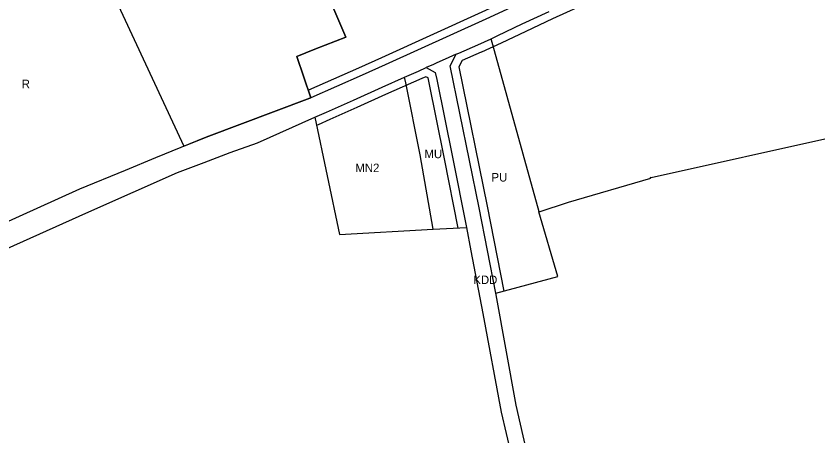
# Model space of a CAD drawing. Extents: x 7435758 to 7439981, y 5550649 to 5554049.
# Drawn here: x 7436617.4 to 7437108.2, y 5551241.1 to 5551497.9 of the extents above; entities that cross this region are included whole.
import ezdxf

# ---------------------------------------------------------------- set-up
doc = ezdxf.new("R2010")
doc.units = 0
for name, color, linetype in [('_Tereny dla których obowiązuje MPZP', 7, 'Continuous'), ('linie_rozgraniczające', 7, 'Continuous'), ('linie_zabudowy_nieprzekraczalne', 7, 'Continuous'), ('oznaczenia_przeznaczen', 7, 'Continuous')]:
    doc.layers.add(name, color=color, linetype=linetype)

msp = doc.modelspace()

# ---------------------------------------------------------------- linework, layer by layer
at = {"layer": '_Tereny dla których obowiązuje MPZP'}
for p, q in [((7436819.25, 5551484.94), (7436803.56, 5551521.54)), ((7436733.75, 5551423.85), (7436797.32, 5551447.57))]:
    msp.add_line(p, q, dxfattribs=at)
for points in [[(7436574.58, 5551700.76), (7436585.89, 5551706.11), (7436720.07, 5551418.24), (7436733.75, 5551423.85)], [(7436789.24, 5551473.16), (7436800.3, 5551477.56), (7436819.25, 5551484.94)], [(7436797.32, 5551447.57), (7436797.85, 5551447.8), (7436789.24, 5551473.16)]]:
    msp.add_lwpolyline(points, dxfattribs=at)
at = {"layer": 'linie_rozgraniczające'}
for p, q in [((7436803.56, 5551521.54), (7436819.25, 5551484.94)), ((7436819.25, 5551484.94), (7436803.56, 5551521.54)), ((7436944.46, 5551514.32), (7436904.86, 5551495.96)), ((7436927.29, 5551493.04), (7436943.73, 5551500.73)), ((7436904.86, 5551495.96), (7436843.44, 5551467.97)), ((7436912.27, 5551485.93), (7436927.29, 5551493.04)), ((7436819.25, 5551484.94), (7436800.3, 5551477.56)), ((7436900.15, 5551480.36), (7436908.19, 5551484.06)), ((7436908.19, 5551484.06), (7436912.27, 5551485.93)), ((7436937.68, 5551378.18), (7436908.19, 5551484.06)), ((7436888.4, 5551475.2), (7436900.15, 5551480.36)), ((7436800.3, 5551477.56), (7436789.24, 5551473.16)), ((7436789.24, 5551473.16), (7436797.85, 5551447.8)), ((7436886.77, 5551474.48), (7436882.22, 5551472.45)), ((7436883.22, 5551467.5), (7436886.77, 5551474.48)), ((7436886.77, 5551474.48), (7436888.4, 5551475.2)), ((7436872.87, 5551468.29), (7436868.46, 5551466.35)), ((7436874.49, 5551469.01), (7436872.87, 5551468.29)), ((7436882.22, 5551472.45), (7436874.49, 5551469.01)), ((7436843.44, 5551467.97), (7436829.23, 5551461.68)), ((7436855.1, 5551460.42), (7436863.74, 5551464.27)), ((7436863.74, 5551464.27), (7436868.46, 5551466.35)), ((7436868.46, 5551466.35), (7436874, 5551463.32)), ((7436900.79, 5551380.63), (7436883.22, 5551467.5)), ((7436829.23, 5551461.68), (7436797.85, 5551447.8)), ((7436841.55, 5551454.42), (7436855.1, 5551460.42)), ((7436855.96, 5551457), (7436855.1, 5551460.42)), ((7436874, 5551463.32), (7436874.95, 5551459.15)), ((7436874.95, 5551459.15), (7436884.6, 5551411.54)), ((7436823.94, 5551446.54), (7436841.55, 5551454.42)), ((7436864.75, 5551412.96), (7436855.96, 5551457)), ((7437006.21, 5551399.25), (7437262.51, 5551456.29)), ((7436797.32, 5551447.57), (7436733.75, 5551423.85)), ((7436733.75, 5551423.85), (7436797.32, 5551447.57)), ((7436797.85, 5551447.8), (7436797.32, 5551447.57)), ((7436807.42, 5551439.12), (7436823.94, 5551446.54)), ((7436800.29, 5551435.97), (7436807.42, 5551439.12)), ((7436765.27, 5551420.25), (7436800.29, 5551435.97)), ((7436800.29, 5551435.97), (7436815.43, 5551364.36)), ((7436733.75, 5551423.85), (7436702.82, 5551411.17)), ((7436748.57, 5551414.38), (7436765.27, 5551420.25)), ((7436732.51, 5551408.24), (7436748.57, 5551414.38)), ((7436702.82, 5551411.17), (7436684.32, 5551403.37)), ((7436872.7, 5551367.51), (7436864.75, 5551412.96)), ((7436884.6, 5551411.54), (7436893.04, 5551368.63)), ((7436716.33, 5551402.22), (7436732.51, 5551408.24)), ((7436684.32, 5551403.37), (7436656.21, 5551391.97)), ((7436662.06, 5551378.16), (7436716.33, 5551402.22)), ((7436955.53, 5551384.01), (7437006.02, 5551398.84)), ((7437006.02, 5551398.84), (7437005.84, 5551399.4)), ((7437005.84, 5551399.4), (7437006.21, 5551399.25)), ((7436656.21, 5551391.97), (7436576.92, 5551356.38)), ((7436911.09, 5551328.35), (7436900.79, 5551380.63)), ((7436937.68, 5551378.18), (7436955.53, 5551384.01)), ((7436583.63, 5551343.04), (7436662.06, 5551378.16)), ((7436937.41, 5551378.09), (7436937.68, 5551378.18)), ((7436948.99, 5551338.64), (7436937.41, 5551378.09)), ((7436815.43, 5551364.36), (7436872.7, 5551367.51)), ((7436872.7, 5551367.51), (7436893.04, 5551368.63)), ((7436893.04, 5551368.63), (7436895.84, 5551354.37)), ((7436895.84, 5551354.37), (7436903.11, 5551315.88)), ((7436911.09, 5551328.35), (7436948.99, 5551338.64)), ((7436911.26, 5551327.44), (7436911.09, 5551328.35)), ((7436923.53, 5551259.89), (7436911.26, 5551327.44)), ((7436903.11, 5551315.88), (7436914.38, 5551255.61)), ((7436931.05, 5551227.33), (7436923.53, 5551259.89)), ((7436914.38, 5551255.61), (7436921.72, 5551223.76))]:
    msp.add_line(p, q, dxfattribs=at)
for points in [[(7436574.58, 5551700.76), (7436585.89, 5551706.11), (7436720.07, 5551418.24), (7436733.75, 5551423.85)], [(7436789.24, 5551473.16), (7436800.3, 5551477.56), (7436819.25, 5551484.94)], [(7436797.32, 5551447.57), (7436797.85, 5551447.8), (7436789.24, 5551473.16)]]:
    msp.add_lwpolyline(points, dxfattribs=at)
at = {"layer": 'linie_zabudowy_nieprzekraczalne'}
for points in [[(7437111.79, 5551562.68), (7437102.24, 5551559.75), (7437093.19, 5551556.77), (7437080.95, 5551552.29), (7437066.27, 5551546.54), (7437046.01, 5551538.55), (7437025.28, 5551530.34), (7437014.86, 5551526.15), (7436995.18, 5551517.99), (7436981.72, 5551512.39), (7436969.29, 5551506.88), (7436945.83, 5551496.2), (7436929.42, 5551488.51), (7436914.41, 5551481.41), (7436914.37, 5551481.39), (7436914.35, 5551481.38), (7436902.24, 5551475.82), (7436902.16, 5551475.79), (7436890.43, 5551470.63), (7436890.42, 5551470.63), (7436888.47, 5551466.79), (7436905.69, 5551381.62), (7436905.69, 5551381.59), (7436915.93, 5551329.65)], [(7436827.24, 5551466.3), (7436841.39, 5551472.53), (7436902.77, 5551500.51), (7436942.36, 5551518.85), (7436942.36, 5551518.86), (7436942.42, 5551518.88), (7436968.79, 5551530.71)], [(7436796.65, 5551452.74), (7436827.26, 5551466.28)], [(7436888.02, 5551368.24), (7436879.7, 5551410.57), (7436870.07, 5551458.1), (7436869.63, 5551460.01), (7436868.22, 5551460.78), (7436865.76, 5551459.7), (7436843.59, 5551449.85), (7436825.98, 5551441.97), (7436809.47, 5551434.56), (7436809.44, 5551434.55), (7436802.32, 5551431.4), (7436801.37, 5551430.97)]]:
    msp.add_lwpolyline(points, dxfattribs=at)

# ---------------------------------------------------------------- texts
at = {"layer": 'oznaczenia_przeznaczen'}
for s, p in [('R', (7436620.93, 5551453.77)), ('MU', (7436867.38, 5551410.99)), ('MN2', (7436825.12, 5551402.42)), ('PU', (7436908.43, 5551396.68)), ('KDD', (7436897.31, 5551333.97))]:
    msp.add_text(s, height=5.2, dxfattribs=at).set_placement(p)

doc.saveas('drawing.dxf')
